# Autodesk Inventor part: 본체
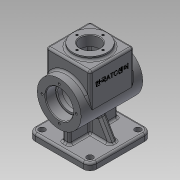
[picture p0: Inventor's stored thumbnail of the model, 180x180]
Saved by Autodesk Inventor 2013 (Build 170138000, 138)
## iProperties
Created: 2019-01
Part Number: 본체
Material: 알루미늄 6061
Document SubType Name: Modeling
Designer: mduedu
Density: 2.40731 g/cm^3
Mass: 734.655 g
Surface Area: 721.983 cm^2
Volume: 305.176 cm^3
Author: mduedu
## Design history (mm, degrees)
sketch "스케치1"
  geometry: C1 r 32 at (0, 0); 1 further point
  constraints: 1 centre point, 1 coincident
  dimensions: "d0" = 64 diameter of C1
extrude "돌출1" new body sketch "스케치1" stored distance "d1" = 90; taper "d2" = 0 deg
sketch "스케치2"
  geometry: L1 (0, 32)-(50, 32); L2 (50, 32)-(50, -32); L3 (50, -32)-(0, -32); L4 (0, -32)-(0, 32); C1 r 32 at (0, 0) reference; 2 further points
  constraints: 8 end point, 2 parallel, 1 coincident, 1 horizontal, 1 midpoint, 1 perpendicular, 1 tangent
  dimensions: "d5" = 50 distance between parallel lines of L4 L2
extrude "돌출2" join sketch "스케치2" stored distance "d7" = 64; taper "d8" = 0 deg
sketch "스케치3"
  geometry: C1 r 25 at (32, 32); 1 further point
  constraints: 1 centre point, 1 coincident
  dimensions: "d9" = 50 diameter of C1
extrude "돌출3" join sketch "스케치3" distance "d10" = 5; taper "d11" = 0 deg
sketch "스케치4"
  geometry: L1 (40, 25)-(0, 25); L2 (0, 25)-(0, -25); L3 (0, -25)-(40, -25); L4 (40, -25)-(40, 25); L5 (55, -25)-(55, 25) reference; A1 r 25 centre (0, 0) between (0, 25) and (0, -25); A2 r 25 centre (0, 0) between (0, -25) and (0, 25); 2 further points
  constraints: 8 end point, 4 point on circle, 2 centre point, 2 coincident, 2 parallel, 1 horizontal, 1 midpoint, 1 perpendicular, 1 tangent
  dimensions: "d12" = 50 diameter of A1; "d13" = 15 distance between parallel lines of L4 L5
extrude "돌출4" cut sketch "스케치4" stored distance "d14" = 48; taper "d15" = 0 deg
sketch "스케치5"
  geometry: C1 r 20 at (0, 0); 1 further point
  constraints: 1 centre point, 1 coincident
  dimensions: "d16" = 40 diameter of C1
extrude "돌출5" cut sketch "스케치5" distance "d17" = 15; taper "d18" = 0 deg
sketch "스케치6"
  geometry: C1 r 17 at (0, 0); 1 further point
  constraints: 1 centre point, 1 coincident
  dimensions: "d19" = 34 diameter of C1
extrude "돌출6" cut sketch "스케치6" stored distance "d20" = 15; taper "d21" = 0 deg
fillet "모깎기1" dims "d22" = 0.3
fillet "모깎기2" dims "d23" = 3
fillet "모깎기3" dims "d24" = 3
fillet "모깎기4" dims "d25" = 3
fillet "모깎기5" dims "d26" = 3
fillet "모깎기6" dims "d27" = 3
sketch "스케치7"
  geometry: C1 r 14 at (0, 0); 1 further point
  constraints: 1 centre point, 1 coincident
  dimensions: "d28" = 28 diameter of C1
extrude "돌출7" cut sketch "스케치7" stored distance "d29" = 15; taper "d30" = 0 deg
chamfer "모따기1" distance "d31" = 1; stored, may be unused: second distance "d32" = 2, angle "d33" = 45 deg
chamfer "모따기2" distance "d34" = 1; stored, may be unused: second distance "d35" = 2, angle "d36" = 45 deg
node "작업 평면1"
sketch "스케치8"
  geometry: L1 (45, -45)-(-45, -45); L2 (-45, -45)-(-45, 45); L3 (-45, 45)-(45, 45); L4 (45, 45)-(45, -45); 3 further points
  constraints: 8 end point, 2 midpoint, 2 parallel, 1 horizontal, 1 horizontal alignment, 1 perpendicular, 1 vertical alignment
  dimensions: "d39" = 90 distance of L1.start L1.end; "d40" = 90 distance of L1.end L2.end
extrude "돌출8" join sketch "스케치8" distance "d41" = 10; taper "d42" = 0 deg
sketch "스케치9"
  geometry: L1 (-35, 5)-(35, 5); L2 (35, 5)-(35, -5); L3 (35, -5)-(-35, -5); L4 (-35, -5)-(-35, 5); 3 further points
  constraints: 8 end point, 2 midpoint, 2 parallel, 1 horizontal, 1 horizontal alignment, 1 perpendicular, 1 vertical alignment
  dimensions: "d52" = 10 distance of L1.end L2.end; "d54" = 70 distance of L1.start L1.end
extrude "돌출9" join sketch "스케치9" stored distance "d50" = 10; taper "d51" = 0 deg
sketch "스케치10"
  geometry: L1 (0, -25)-(37, -25) reference; L2 (40, -22)-(40, -14) reference; L3 (40, -14)-(54, -14) reference; L4 (54, -14)-(55, -15) reference; L5 (55, -15)-(55, -25) reference; L6 (55, -25)-(53, -25) reference; L7 (50, -28)-(50, -29) reference; L8 (47, -32)-(0, -32) reference; L9 (-31.607, -5)-(-55, -5) reference; L10 (-55, -5)-(-55, -45) reference; L11 (-55, -45)-(-65, -45) reference; L12 (-65, -45)-(-65, 45) reference; L13 (-65, 45)-(-55, 45) reference; L14 (-55, 45)-(-55, 5) reference; L15 (-55, 5)-(-31.607, 5) reference; L16 (0, 32)-(47, 32) reference; L17 (50, 29)-(50, 28) reference; L18 (53, 25)-(55, 25) reference; L19 (55, 25)-(55, 15) reference; L20 (55, 15)-(54, 14) reference; L21 (54, 14)-(40, 14) reference; L22 (40, 14)-(40, 22) reference; L23 (37, 25)-(0, 25) reference; L24 (-55, 35)-(-26.2, 18.372); A1 r 25 centre (0, 0) between (0, 25) and (0, -25) reference; A2 r 3 centre (37, -22) between (37, -25) and (40, -22) reference; A3 r 3 centre (53, -28) between (53, -25) and (50, -28) reference; A4 r 3 centre (47, -29) between (47, -32) and (50, -29) reference; A5 r 32 centre (0, 0) between (-31.607, -5) and (0, -32) reference; A6 r 32 centre (0, 0) between (0, 32) and (-31.607, 5) reference; A7 r 3 centre (47, 29) between (50, 29) and (47, 32) reference; A8 r 3 centre (53, 28) between (50, 28) and (53, 25) reference; A9 r 3 centre (37, 22) between (40, 22) and (37, 25) reference; 1 further point
  constraints: 2 end point, 1 point on circle, 1 point on line
  dimensions: "d55" = 35 vertical distance of L24.start point (0, 0); "d56" = 120 deg angle of L24 L14
feature "리브1" sketch "스케치10" dims "d57" = 1, "d58" = 10, "d59" = 0, "d60" = 0, "d61" = 1, "d62" = 1
fillet "모깎기7" dims "d63" = 3
fillet "모깎기8" dims "d64" = 3
fillet "모깎기9" dims "d65" = 10
sketch "스케치11"
  geometry: L1 (-45, 35)-(-45, -35) reference; L2 (-35, -45)-(35, -45) reference; L3 (45, -35)-(45, 35) reference; L4 (35, 45)-(-35, 45) reference; L5 (8, -29.804)-(8, -8) reference; L6 (-2, -36.732)-(2, -36.732) reference; L7 (-8, -8)-(-8, -29.804) reference; L8 (-32, -8)-(-8, -8) reference; L9 (-38, 2)-(-38, -2) reference; L10 (-8, 8)-(-32, 8) reference; L11 (-8, 29.804)-(-8, 8) reference; L12 (2, 36.732)-(-2, 36.732) reference; L13 (8, 8)-(8, 29.804) reference; L14 (32, 8)-(8, 8) reference; L15 (38, -2)-(38, 2) reference; L16 (8, -8)-(32, -8) reference; A1 r 10 centre (-35, 35) between (-35, 45) and (-45, 35) reference; A2 r 10 centre (-35, -35) between (-45, -35) and (-35, -45) reference; A3 r 10 centre (35, -35) between (35, -45) and (45, -35) reference; A4 r 10 centre (35, 35) between (45, 35) and (35, 45) reference; A5 r 6 centre (-32, -2) between (-38, -2) and (-32, -8) reference; A6 r 6 centre (-32, 2) between (-32, 8) and (-38, 2) reference; A7 r 6 centre (32, 2) between (38, 2) and (32, 8) reference; A8 r 6 centre (32, -2) between (32, -8) and (38, -2) reference; 9 further points; 4 other entities
  constraints: 4 coincident, 4 other
hole "구멍1" sketch "스케치11" at (-35, 35), (35, 35), (35, -35), (-35, -35) diameter "d66" = 9; stored, may be unused: countersink angle "d70" = 90 deg, drill point angle "d72" = 118 deg; dims "d67" = 6, "d68" = 4, "d69" = 2, "d71" = 8
fillet "모깎기10" dims "d73" = 3
sketch "스케치12"
  geometry: L1 (-3, 47)-(-3, 19.596) reference; 2 further points
  constraints: 1 other
  dimensions: "d74" = 32 distance from line of point (29, 30) L1; "d75" = 30 distance of point (29, 30) point (29, 0)
feature "엠보싱1" sketch "스케치12" dims "d76" = 0.5, "d77" = 0
sketch "스케치13"
  geometry: 4 further points
  constraints: 4 other
hole "구멍2" sketch "스케치13" at (-25, 0), (0, -25), (25, 0), (0, 25) diameter "d78" = 3.242; stored, may be unused: countersink angle "d82" = 90 deg, drill point angle "d84" = 120 deg; dims "d79" = 7, "d80" = 4, "d81" = 2, "d83" = 9
sketch "스케치14"
  geometry: 4 further points
  constraints: 4 other
hole "구멍3" sketch "스케치14" at (-25, 0), (0, -25), (25, 0), (0, 25) diameter "d85" = 3.242; stored, may be unused: countersink angle "d89" = 90 deg, drill point angle "d91" = 120 deg; dims "d86" = 7, "d87" = 4, "d88" = 2, "d90" = 9
sketch "스케치15"
  geometry: 4 further points
  constraints: 4 other
hole "구멍4" sketch "스케치15" at (0, -19), (19, 0), (0, 19), (-19, 0) diameter "d92" = 3.242; stored, may be unused: countersink angle "d96" = 90 deg, drill point angle "d98" = 120 deg; dims "d93" = 8, "d94" = 4, "d95" = 2, "d97" = 10
node "솔리드1"
mirror "대칭1"
mirror "대칭2"
node "투영된 루프1"
node "절단 모서리 투영1"
node "절단 모서리 투영2"
other parameters: "d37" = -65
